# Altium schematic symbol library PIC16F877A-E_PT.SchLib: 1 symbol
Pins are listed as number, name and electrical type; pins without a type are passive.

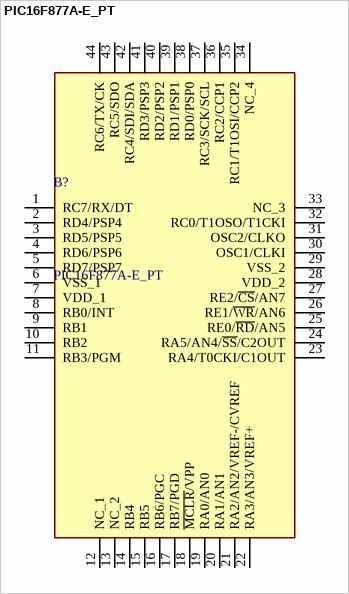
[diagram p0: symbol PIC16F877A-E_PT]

## PIC16F877A-E_PT
designator B?
8-bit Microcontrollers - MCU 14KB 368 RAM 33 I/O; Manufacturer_Name: Microchip; Manufacturer_Part_Number: PIC16F877A-E/PT; Geometry.Height: 1.2mm
footprint QFP80P1200X1200X120-44N
pins: 1 RC7/RX/DT, 2 RD4/PSP4, 3 RD5/PSP5, 4 RD6/PSP6, 5 RD7/PSP7, 6 VSS_1, 7 VDD_1, 8 RB0/INT, 9 RB1, 10 RB2, 11 RB3/PGM, 12 NC_1, 13 NC_2, 14 RB4, 15 RB5, 16 RB6/PGC, 17 RB7/PGD, 18 ~{MCLR}/VPP, 19 RA0/AN0, 20 RA1/AN1, 21 RA2/AN2/VREF-/CVREF, 22 RA3/AN3/VREF+, 23 RA4/T0CKI/C1OUT, 24 RA5/AN4/~{SS}/C2OUT, 25 RE0/~{RD}/AN5, 26 RE1/~{WR}/AN6, 27 RE2/~{CS}/AN7, 28 VDD_2, 29 VSS_2, 30 OSC1/CLKI, 31 OSC2/CLKO, 32 RC0/T1OSO/T1CKI, 33 NC_3, 34 NC_4, 35 RC1/T1OSI/CCP2, 36 RC2/CCP1, 37 RC3/SCK/SCL, 38 RD0/PSP0, 39 RD1/PSP1, 40 RD2/PSP2, 41 RD3/PSP3, 42 RC4/SDI/SDA, 43 RC5/SDO, 44 RC6/TX/CK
